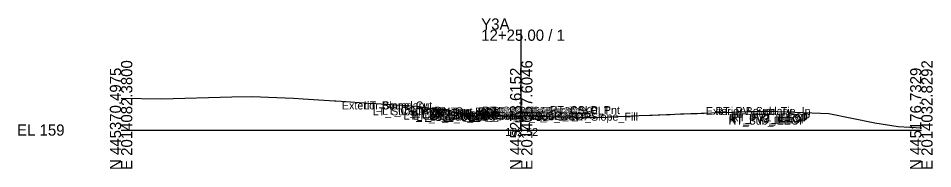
# Model space of a CAD drawing. Extents: x -26 to 205, y -10 to 5029.
# Drawn here: x -25.7 to 202.8, y 4490.3 to 4528 of the extents above; entities that cross this region are included whole.
import ezdxf

# ---------------------------------------------------------------- set-up
doc = ezdxf.new("R2010")
doc.units = 0
for name, color, linetype in [('Default', 7, 'Continuous'), ('Exist Cross Section Cell', 7, 'Continuous'), ('Exist XS Center Line Elevation Label', 7, 'Continuous'), ('Exist XS Ground Line', 7, 'Continuous'), ('Scratch_Level_0', 7, 'Continuous')]:
    doc.layers.add(name, color=color, linetype=linetype)

msp = doc.modelspace()

# ---------------------------------------------------------------- linework, layer by layer
at = {"layer": 'Exist Cross Section Cell'}
for p, q in [((100, 4500), (100, 4525.15)), ((0, 4500), (100, 4500)), ((100, 4500), (200, 4500))]:
    msp.add_line(p, q, dxfattribs=at)
at = {"layer": 'Exist XS Ground Line'}
msp.add_lwpolyline([(0, 4507.95), (10.07, 4507.83), (27.7, 4508.33), (32.73, 4508.38), (38.95, 4508.15), (43.05, 4508.01), (45.48, 4507.79), (53.37, 4507.35), (53.7, 4507.33), (54.99, 4507.26), (61.92, 4506.77), (63.69, 4506.66), (70.14, 4506.19), (74.02, 4506.01), (81.63, 4504.7), (86.96, 4503.72), (88.32, 4503.56), (90.82, 4503.55), (100, 4503.52), (103.59, 4503.51), (110.63, 4503.33), (118.23, 4503.11), (118.91, 4503.12), (121.43, 4503.25), (121.92, 4503.27), (122.57, 4503.3), (124.32, 4503.38), (126, 4503.45), (126.93, 4503.49), (128.07, 4503.55), (129.51, 4503.61), (132.04, 4503.73), (132.71, 4503.75), (134.22, 4503.81), (134.61, 4503.83), (136.29, 4503.9), (137.2, 4503.93), (138.35, 4503.97), (139.8, 4504.03), (140.63, 4504.06), (142.36, 4504.13), (142.71, 4504.14), (143.04, 4504.15), (143.97, 4504.18), (144.98, 4504.22), (145.73, 4504.24), (147.52, 4504.3), (149.12, 4504.36), (150.07, 4504.4), (152.63, 4504.5), (152.98, 4504.51), (154.76, 4504.55), (155.22, 4504.57), (156.82, 4504.61), (157.81, 4504.64), (158.9, 4504.67), (160.29, 4504.72), (161.15, 4504.73), (162.01, 4504.75), (176.85, 4504.13), (188.35, 4501.84), (194.21, 4500.85), (200, 4500.59)], dxfattribs=at)

# ---------------------------------------------------------------- texts
at = {"layer": 'Default'}
msp.add_text('-', height=0.0001, dxfattribs=at).set_placement((0, 4500))
at = {"layer": 'Exist Cross Section Cell'}
for s, p in [('Y3A', (90, 4525.15)), ('12+25.00 / 1', (90, 4522.35)), ('EL 159', (-26, 4498.6))]:
    msp.add_text(s, height=2.8, dxfattribs=at).set_placement(p)
for s, p in [('E 2014082.3800', (2.8, 4490)), ('E 2014057.6046', (102.8, 4490)), ('E 2014032.8292', (202.8, 4490)), ('N 445370.4975', (0, 4490)), ('N 445273.6152', (100, 4490)), ('N 445176.7329', (200, 4490))]:
    msp.add_text(s, height=2.8, rotation=90, dxfattribs=at).set_placement(p)
at = {"layer": 'Exist XS Center Line Elevation Label'}
msp.add_text('162.52', height=2, dxfattribs=at).set_placement((96.03, 4498.52))
at = {"layer": 'Scratch_Level_0'}
for s, p in [('Exterior Boundary', (55.18, 4505.16)), ('LT_Slope_Cut', (60.68, 4505.16)), ('LT_Sub_Trench_Out_DLT', (62.87, 4503.68)), ('LT_CSLP_Pnt', (65.22, 4503.83)), ('LT_CG1_Shelf_Out', (70.6, 4502.62)), ('LT_CG_Top_Face', (72.31, 4503.64)), ('LT_CG_Top_BOC', (72.83, 4503.64)), ('LT_CG_Bot_BOC', (72.87, 4502.63)), ('LT_CG_Top_Gut', (73.29, 4503.14)), ('LT_Sub_OEOP', (73.82, 4502.28)), ('LT_CG_Bot_IE', (76.97, 4502.68)), ('LT_Sub_OEOT', (77.13, 4502.34)), ('LT_PV2_OEOT', (77.23, 4503.01)), ('LT_PV3_OEOT', (77.23, 4502.68)), ('LT_PV1_OEOT', (77.79, 4503.26)), ('RT_Sub_OEEOP', (89.17, 4502.6)), ('LT_Sub_OEEOP', (89.21, 4502.6)), ('RT_PV2_OEEOP', (89.26, 4503.27)), ('RT_PV3_OEEOP', (89.26, 4502.93)), ('LT_PV2_OEEOP', (89.31, 4503.27)), ('LT_PV3_OEEOP', (89.31, 4502.93)), ('RT_PV1_OEEOP', (89.83, 4503.39)), ('LT_PV1_OEEOP', (89.87, 4503.39)), ('LT_PV2_IEEOP', (89.95, 4503.27)), ('RT_Sub_Trench_Out_DLT', (90.27, 4503.84)), ('LT_PV1_IEEOP', (90.52, 4503.39)), ('Sub_PGL', (93.81, 4502.6)), ('PV2_PGL', (93.91, 4503.27)), ('PV3_PGL', (93.91, 4502.93)), ('RT_CG_Top_Face', (94.21, 4503.8)), ('PV1_PGL', (94.47, 4503.52)), ('RT_CG1_Shelf_Out', (94.5, 4502.77)), ('RT_CG_Bot_IE', (94.87, 4502.83)), ('RT_Sub_OEOT', (95.03, 4502.5)), ('RT_PV2_OEOT', (95.13, 4503.17)), ('RT_PV3_OEOT', (95.13, 4502.83)), ('RT_CG_Top_Gut', (95.19, 4503.3)), ('RT_PV1_OEOT', (95.69, 4503.42)), ('RT_CG_Top_BOC', (95.74, 4503.8)), ('RT_CG_Bot_BOC', (95.77, 4502.78)), ('RT_Sub_OEOP', (98.4, 4502.43)), ('RT_CSLP_Pnt', (107.13, 4503.99)), ('RT_Slope_Fill', (112.39, 4502.35)), ('Exterior Boundary', (146.14, 4503.75)), ('RT_PV_Sub_Tie_In', (148.52, 4503.75)), ('RT_Sub_IEEOP', (151.79, 4501.36)), ('RT_PV2_IEEOP', (151.89, 4502.03)), ('RT_PV3_IEEOP', (151.89, 4501.69)), ('RT_PV1_IEEOP', (152.46, 4502.15))]:
    msp.add_text(s, height=2, dxfattribs=at).set_placement(p)

doc.saveas('drawing.dxf')
